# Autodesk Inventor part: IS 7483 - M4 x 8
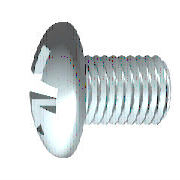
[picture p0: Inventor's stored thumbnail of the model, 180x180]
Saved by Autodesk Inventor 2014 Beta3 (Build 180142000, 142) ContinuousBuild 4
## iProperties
IsCustomPart: 0
Created: 2010-02
Part Number: IS 7483 - M4 x 8
Material: Steel, Mild
Description: Specification for Cross Recessed Pan Head Screws
Document SubType Name: Modeling
Standard: IS 7483
Designer: Thom Tremblay
Standards Organization: IS
Language: en-US
Size Designation: M4 x 8
Categories: <MemberInstance><Categories><Category DisplayName="Fasteners" InternalName="e4da775c-781d-43d5-af7c-5136215cf5a6" Mnemonic="FSTN"><Category DisplayName="Bolts"
Density: 1 g/cm^3
Appearance: Steel
Author: Thom Tremblay
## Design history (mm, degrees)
workplane "Work Plane3"
sketch "Sketch2"
  geometry: L1 (-5.513, 0)-(5.513, 0) reference; L2 (0, -5.513)-(0, 5.513) reference; L3 (0, 2.2)-(0, 0); L4 (0, 0)-(2.2, 0); L5 (0, 0)-(2.785, 2.785); L6 (0.415, 2.161)-(0.386, 0.666); L7 (2.161, 0.415)-(0.666, 0.386); L8 (0.415, -2.161)-(0.386, -0.666); L9 (2.161, -0.415)-(0.666, -0.386); L10 (-0.415, 2.161)-(-0.386, 0.666); L11 (-2.161, 0.415)-(-0.666, 0.386); L12 (-2.161, -0.415)-(-0.666, -0.386); L13 (-0.415, -2.161)-(-0.386, -0.666); A1 r 0.66 centre (0, 0) between (0.66, 0) and (0, 0.66); A2 r 2.2 centre (0, 0) between (2.2, 0) and (2.161, 0.415); A3 r 2.2 centre (0, 0) between (0.415, 2.161) and (0, 2.2); A4 r 2.2 centre (0, 0) between (2.161, 0.415) and (0.415, 2.161); A5 r 2.2 centre (0, 0) between (0, -2.2) and (0.415, -2.161); A6 r 2.2 centre (0, 0) between (0.415, -2.161) and (2.161, -0.415); A7 r 2.2 centre (0, 0) between (2.161, -0.415) and (2.2, 0); A8 r 2.2 centre (0, 0) between (-2.161, 0.415) and (-2.2, 0); A9 r 2.2 centre (0, 0) between (-0.415, 2.161) and (-2.161, 0.415); A10 r 2.2 centre (0, 0) between (0, 2.2) and (-0.415, 2.161); A11 r 2.2 centre (0, 0) between (-2.2, 0) and (-2.161, -0.415); A12 r 2.2 centre (0, 0) between (-2.161, -0.415) and (-0.415, -2.161); A13 r 2.2 centre (0, 0) between (-0.415, -2.161) and (0, -2.2); A14 r 0.77 centre (0, 0) between (0.77, 0) and (0, 0.77); A15 r 0.275 centre (0.661, 0.661) between (0.386, 0.666) and (0.666, 0.386); A16 r 0.275 centre (0.661, -0.661) between (0.666, -0.386) and (0.386, -0.666); A17 r 0.275 centre (-0.661, 0.661) between (-0.666, 0.386) and (-0.386, 0.666); A18 r 0.275 centre (-0.661, -0.661) between (-0.386, -0.666) and (-0.666, -0.386); 1 further point
  constraints: 38 point on circle, 22 end point, 19 symmetric about line, 18 centre point, 4 coincident, 3 collinear, 3 point on line, 3 tangent, 1 perpendicular, 21 other
  dimensions: "d4" = 45 deg angle of L5 L4; "d5" = 1.32 diameter of A1 (= 0.3 x SDM); "d6" = 4.4 diameter of A4 (= SDM); "d7" = 0.415 distance from line of L6.start L3 (= 0.5 x SBR); "d14" = 1.54 diameter of A14 (= 0.35 x SDM)
extrude "Slot" join sketch "Sketch2" taper "d15" = 5 deg; stored distance "d54" = 10
revolve "Cut" stored, may be unused: angle "d56" = 90 deg
revolve "Body" stored, may be unused: angle "d18" = 90 deg
body "Solid1"
sketch "Sketch1"
  geometry: L1 (8, 0)-(8, 2); L2 (8, 2)-(1.4, 2); L3 (3.962, 5.08)-(3.962, 5.08); L4 (-3.1, 0)-(-3.1, 3.892); L5 (-2.773, 2.037)-(-1.426, 1.365); L6 (-1.426, 1.365)-(-0.7, 0); L7 (-0.7, 0)-(8, 0); L8 (-5.708, 0)-(10.285, 0) reference; L9 (0, -1.016)-(0, 6.096) reference; L10 (-2.773, 2.037)-(-3.1, 2.2); L11 (-1.771, 3.938)-(-3.1, 3.892); L12 (-1.771, 3.938)-(0, 4); L13 (0, 4)-(0, 1.811); L14 (0, 1.811)-(0.971, 1.811); L15 (0.971, 1.811)-(1.4, 2); L16 (1.4, 2)-(0, 2); A1 r 6.5 centre (3.4, 0) between (-1.771, 3.938) and (-3.1, 0)
  constraints: 28 end point, 5 point on line, 4 collinear, 4 point on circle, 3 parallel, 2 perpendicular, 1 centre point, 1 horizontal, 1 tangent
  dimensions: "d1" = 4 diameter of L2 L7 (= GD); "d2" = 2.4 distance from line of L6.end L4 (= STI); "d11" = 4.4 diameter of L10.end L7 (= SDM); "d12" = 62 deg angle of L6 L7; "d13" = 26.5 deg angle of L5 L7; "d17" = 8 diameter of L12.end L7 (= KOD); "d19" = 2 deg angle of L12 L7 (= KEWI); "d20" = 3.1 distance between parallel lines of L4 L13 (= KOH); "d21" = 6.5 radius of A1 (= KR); "d23" = 3.62111 diameter of L14 L7 (= BDM); "d24" = 6.6 distance of L1.end L2.end (= GEL); "d25" = 0.42941 horizontal distance of L14.end L2.end (= GAL); "d28" = 8 distance between parallel lines of L1 L13 (= NLG)
workplane "Work Plane1"
fillet "Fillet1" dims "d29" = 1.3 (= RR)
fillet "Fillet2" dims "d16" = 0.166 (= 0.2 x SBR)
feature "Thread" dims "d8" = 6.6 (= GEL), "d9" = 0
chamfer "Chamfer1" distance "d26" = 0.42941 (= -0.5 x SPD + 0.5 x GD); stored, may be unused: second distance "d27" = 0.42952 (computed from GUL), angle "d78" = 45 deg
other parameters: "GD" = 4 (= NND) [user parameter; used in 2 equation terms], "NLG" = 8 [user parameter; used in 1 equation term], "GEL" = 6.6 [user parameter; used in 2 equation terms], "KOD" = 8 [user parameter; used in 1 equation term], "KOH" = 3.1 [user parameter; used in 2 equation terms], "SDM" = 4.4 [user parameter; used in 4 equation terms], "STI" = 2.4 [user parameter; used in 1 equation term], "SBR" = 0.83 [user parameter; used in 2 equation terms], "GAL" = 0.42941 (= 0.61345 x PTC) [user parameter; used in 1 equation term], "SPD" = 3.14117 (= NND - 1.2269 x PTC) [user parameter; used in 1 equation term], "KEWI" = 2 deg [user parameter; used in 1 equation term], "d3" = -3.1 (= -KOH), "d10" = 0, "KR" = 6.5 [user parameter; used in 1 equation term], "BDM" = 3.62111 [user parameter; used in 1 equation term], "GUL" = 0.42941 (= 0.61345 x PTC) [user parameter; used in 1 equation term], "RR" = 1.3 [user parameter; used in 1 equation term], "d79" = 0, "d80" = 0, "PTC" = 0.7 [user parameter; used in 5 equation terms], "THREADDIA" = 4 [user parameter; used in 1 equation term], "TOA" = 30 deg [user parameter], "TPU" = 14.28571 (computed from PTC) [user parameter], "NND" = 4 [user parameter; used in 2 equation terms], "GD1" = 3.14117 (= THREADDIA - 1.2269 x PTC) [user parameter]
